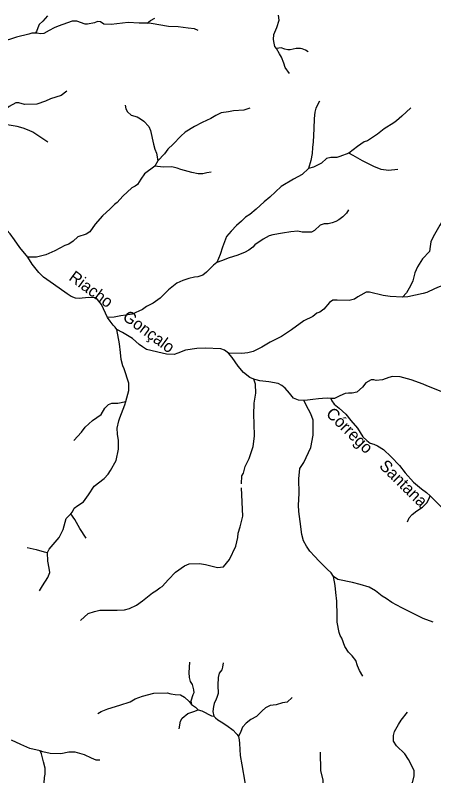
# Model space of a CAD drawing. Extents: x 717.8 to 772.7, y 8672.2 to 8728.
# Drawn here: x 756.1 to 763.19, y 8714.76 to 8727.64 of the extents above; entities that cross this region are included whole.
import ezdxf
from ezdxf.enums import TextEntityAlignment as Align

# ---------------------------------------------------------------- set-up
doc = ezdxf.new("R2010")
doc.units = 0
doc.header["$LTSCALE"] = 0.08
doc.linetypes.add('LONG_DASHED', pattern=[7.5, 6, -1.5])
doc.layers.add('61', color=7, linetype='Continuous')
doc.layers.add('9', color=7, linetype='LONG_DASHED', lineweight=25)

msp = doc.modelspace()

# ---------------------------------------------------------------- linework, layer by layer
at = {"layer": '9'}
msp.add_line((758.5196, 8725.1691), (758.4648, 8725.0777), dxfattribs=at)
for points in [[(756.6486, 8727.6249), (756.573, 8727.5356), (756.5072, 8727.4786), (756.4853, 8727.4211), (756.4612, 8727.3607), (756.4406, 8727.3316)], [(758.3358, 8727.5043), (758.3937, 8727.5448), (758.469, 8727.5876)], [(760.5259, 8727.0735), (760.4994, 8727.1071), (760.4855, 8727.166), (760.4753, 8727.2276), (760.4832, 8727.3107), (760.534, 8727.4283), (760.572, 8727.5508), (760.5609, 8727.637)], [(758.3358, 8727.5043), (758.2024, 8727.5046), (758.0148, 8727.5146), (757.7287, 8727.4781), (757.6046, 8727.4838), (757.548, 8727.5256), (757.495, 8727.5314), (757.4456, 8727.5062), (757.3301, 8727.4836), (757.2879, 8727.4846), (757.1487, 8727.5367), (757.07, 8727.5367), (756.8313, 8727.4533), (756.7625, 8727.4206), (756.678, 8727.3781), (756.5869, 8727.3274), (756.5251, 8727.3236), (756.4774, 8727.3302), (756.4406, 8727.3316)], [(759.2033, 8727.3802), (759.1405, 8727.4046), (759.0332, 8727.417), (758.8636, 8727.4417), (758.6968, 8727.4472), (758.4026, 8727.4957), (758.3358, 8727.5043)], [(756.4406, 8727.3316), (756.3851, 8727.3307), (756.3369, 8727.3185), (756.1262, 8727.2669), (755.8644, 8727.1781), (755.7217, 8727.1203), (755.5081, 8726.9775), (755.4349, 8726.8991), (755.3341, 8726.7685), (755.2591, 8726.6938), (755.139, 8726.5879), (755.0338, 8726.4895), (754.923, 8726.4081), (754.7553, 8726.2679), (754.5882, 8726.0904), (754.4922, 8726.0084), (754.3818, 8725.9344), (754.2874, 8725.8947)], [(761.0652, 8727.0151), (761.0157, 8727.0437), (760.9584, 8727.0685), (760.9313, 8727.0746), (760.8581, 8727.0723), (760.7571, 8727.0522), (760.7161, 8727.0522), (760.6658, 8727.063), (760.6076, 8727.082), (760.5259, 8727.0735)], [(760.7472, 8726.6503), (760.6744, 8726.751), (760.6528, 8726.8227), (760.6102, 8726.9245), (760.5762, 8726.981), (760.5259, 8727.0735)], [(756.9762, 8726.3485), (756.8833, 8726.2784), (756.6995, 8726.2187), (756.6152, 8726.1826), (756.4684, 8726.1324), (756.2621, 8726.1268), (756.1651, 8726.153), (756.1115, 8726.1515), (755.9995, 8726.0901), (755.8472, 8725.968), (755.7044, 8725.9013)], [(761.2537, 8726.1833), (761.1949, 8726.0606), (761.1753, 8725.9966), (761.1617, 8725.8884), (761.1573, 8725.7144), (761.1463, 8725.4937), (761.1358, 8725.394), (761.1279, 8725.2931), (761.1097, 8725.1745), (761.0668, 8725.0402)], [(757.9634, 8726.113), (757.9766, 8726.0535), (758.0068, 8726.0007), (758.0682, 8725.9469), (758.1654, 8725.9157), (758.2239, 8725.8836), (758.2833, 8725.8449), (758.3683, 8725.7514), (758.3927, 8725.6835), (758.4446, 8725.4503), (758.4673, 8725.371), (758.4937, 8725.3012), (758.5196, 8725.1691)], [(760.0753, 8726.0603), (759.9715, 8726.0308), (759.7998, 8726.0148), (759.7139, 8725.9997), (759.5889, 8725.9812), (759.4978, 8725.9402), (759.4153, 8725.8902), (759.269, 8725.8173), (759.141, 8725.7536), (758.9778, 8725.6541), (758.9058, 8725.588), (758.778, 8725.4535), (758.6897, 8725.3675), (758.6306, 8725.2916), (758.5196, 8725.1691)], [(762.8008, 8726.0673), (762.6475, 8725.9255), (762.5572, 8725.847), (762.511, 8725.815), (762.3495, 8725.7152), (762.2383, 8725.6196), (762.0697, 8725.5099), (762.0092, 8725.4924), (761.8983, 8725.4163), (761.7511, 8725.3015)], [(756.6542, 8725.4873), (756.4013, 8725.6568), (756.3419, 8725.6824), (756.2368, 8725.7241), (756.1352, 8725.7512), (756.0337, 8725.7675), (755.9011, 8725.7913), (755.766, 8725.851), (755.7044, 8725.9013)], [(761.7511, 8725.3015), (761.5977, 8725.2414), (761.5457, 8725.2269), (761.446, 8725.226), (761.371, 8725.2081), (761.2858, 8725.1297), (761.1503, 8725.0615), (761.0668, 8725.0402)], [(762.5787, 8725.0253), (762.4208, 8725.0099), (762.2958, 8725.0218), (762.1764, 8725.0749), (762.0605, 8725.1315), (761.9851, 8725.1725), (761.8253, 8725.2612), (761.7511, 8725.3015)], [(758.4648, 8725.0777), (758.2907, 8724.9489), (758.2322, 8724.8621), (758.1713, 8724.7715), (758.1351, 8724.7432), (758.0785, 8724.713), (757.9243, 8724.5702), (757.8322, 8724.4629), (757.786, 8724.4308), (757.7123, 8724.3598), (757.584, 8724.2381), (757.4585, 8724.0993), (757.3651, 8723.97), (757.3056, 8723.9312), (757.1622, 8723.8822), (757.0848, 8723.8095), (757.0131, 8723.7595), (756.9413, 8723.7369), (756.7759, 8723.6443), (756.6229, 8723.5772), (756.4627, 8723.5393), (756.3163, 8723.5385)], [(759.4222, 8724.9763), (759.3458, 8724.9678), (759.2807, 8724.9518), (759.2014, 8724.9518), (759.0929, 8724.9725), (758.9051, 8725.0254), (758.8447, 8725.0443), (758.7522, 8725.0669), (758.6069, 8725.0622), (758.4648, 8725.0777)], [(761.0668, 8725.0402), (760.9593, 8724.9385), (760.8152, 8724.8591), (760.6037, 8724.7345), (760.4143, 8724.5569), (760.3199, 8724.4756), (760.1835, 8724.3526), (760.0734, 8724.2613), (760.0018, 8724.2146), (759.9346, 8724.1482), (759.8516, 8724.0784), (759.7594, 8723.9778), (759.6776, 8723.8878), (759.6101, 8723.7062), (759.5735, 8723.5872), (759.5185, 8723.45)], [(763.5982, 8724.7803), (763.5611, 8724.6423), (763.5026, 8724.5196), (763.4686, 8724.4639), (763.4394, 8724.3752), (763.3687, 8724.2027), (763.2936, 8724.0797), (763.176, 8723.8834), (763.1407, 8723.7986), (763.129, 8723.7209), (763.1181, 8723.6332), (762.9961, 8723.5095), (762.9156, 8723.3784), (762.8687, 8723.2762), (762.836, 8723.1411), (762.7934, 8723.0515), (762.7274, 8722.9371), (762.6587, 8722.8609)], [(761.748, 8724.3382), (761.7094, 8724.2822), (761.6488, 8724.2207), (761.5845, 8724.1704), (761.5309, 8724.1421), (761.4688, 8724.1205), (761.4022, 8724.1048), (761.3353, 8724.1045), (761.2663, 8724.08), (761.1689, 8723.9898), (761.1172, 8723.9625), (760.9593, 8723.9644), (760.8888, 8723.9784), (760.7713, 8723.9671), (760.6302, 8723.9483), (760.4629, 8723.9178), (760.4044, 8723.9032), (760.2989, 8723.8467), (760.1605, 8723.7487), (760.1286, 8723.7061), (760.0604, 8723.6592), (759.9869, 8723.6166), (759.8574, 8723.5702), (759.7249, 8723.5279), (759.5939, 8723.48), (759.5185, 8723.45)], [(756.3163, 8723.5385), (756.1824, 8723.7026), (756.09, 8723.8301), (756.0192, 8723.9359), (755.9633, 8723.9978), (755.8208, 8724.0337), (755.7087, 8724.0529), (755.6195, 8724.0675)], [(757.6668, 8722.5198), (757.5669, 8722.7401), (757.4753, 8722.8486), (757.3423, 8722.8536), (757.1857, 8722.8376), (757.1249, 8722.8424), (757.0484, 8722.8726), (756.9819, 8722.9175), (756.8451, 8723.0131), (756.6931, 8723.1211), (756.5832, 8723.199), (756.5025, 8723.2789), (756.3914, 8723.4196), (756.3163, 8723.5385)], [(759.5185, 8723.45), (759.4611, 8723.4034), (759.3393, 8723.2858), (759.2771, 8723.2361), (759.1947, 8723.2054), (759.1382, 8723.2023), (759.0451, 8723.1807), (758.9394, 8723.1461), (758.8411, 8723.0997), (758.6967, 8722.9861), (758.5558, 8722.8447), (758.4407, 8722.7615), (758.328, 8722.7016), (758.2583, 8722.6537), (758.0843, 8722.5768), (757.9764, 8722.5586), (757.8925, 8722.5482), (757.7791, 8722.5251), (757.6668, 8722.5198)], [(764.1283, 8723.3948), (763.9194, 8723.3238), (763.7448, 8723.2539), (763.6375, 8723.1892), (763.538, 8723.1429), (763.5043, 8723.1083), (763.2782, 8723.0347), (763.2029, 8723.001), (763.0692, 8722.9417), (763.0088, 8722.9221), (762.7509, 8722.8653), (762.6587, 8722.8609)], [(762.6587, 8722.8609), (762.4535, 8722.8746), (762.334, 8722.8905), (762.1034, 8722.9447), (762.0472, 8722.9461), (761.9532, 8722.8968), (761.9038, 8722.8659), (761.8489, 8722.8254), (761.7555, 8722.8068), (761.5538, 8722.813), (761.479, 8722.8085), (761.4247, 8722.7714), (761.328, 8722.6581), (761.2614, 8722.6102), (761.212, 8722.5917), (761.1393, 8722.534), (760.9876, 8722.4599), (760.7822, 8722.3103), (760.6107, 8722.195), (760.4171, 8722.1002), (760.2792, 8722.013), (760.1323, 8721.9409), (760.0424, 8721.919), (759.9395, 8721.9087), (759.712, 8721.9115)], [(757.8255, 8722.3149), (757.7955, 8722.3516), (757.7619, 8722.3857), (757.7091, 8722.4534), (757.6668, 8722.5198)], [(759.712, 8721.9115), (759.6491, 8721.9648), (759.5869, 8721.9878), (759.3171, 8721.9967), (759.1778, 8721.9953), (758.9871, 8721.9671), (758.8567, 8721.9145), (758.7966, 8721.893), (758.6654, 8721.8967), (758.5925, 8721.9108), (758.3257, 8721.9782), (758.2575, 8722.0183), (758.2012, 8722.062), (758.0878, 8722.1614), (757.9208, 8722.2639), (757.8255, 8722.3149)], [(757.9743, 8721.0945), (758.0253, 8721.2793), (758.0242, 8721.4082), (757.9454, 8721.6469), (757.9252, 8721.7001), (757.8965, 8721.8088), (757.8869, 8721.926), (757.8688, 8722.0741), (757.8255, 8722.3149)], [(760.1429, 8721.4759), (760.0728, 8721.4999), (759.9688, 8721.5873), (759.8777, 8721.6932), (759.7762, 8721.8395), (759.712, 8721.9115)], [(757.2072, 8717.3871), (757.3407, 8717.5046), (757.4476, 8717.5409), (757.5382, 8717.563), (757.8268, 8717.5583), (757.953, 8717.5667), (758.0404, 8717.5874), (758.156, 8717.6448), (758.2566, 8717.7191), (758.4257, 8717.8555), (758.4859, 8717.8885), (758.5541, 8717.9384), (758.5902, 8717.9624), (758.6982, 8718.0826), (758.8183, 8718.2028), (758.9682, 8718.3107), (759.049, 8718.3465), (759.2258, 8718.3493), (759.3264, 8718.3361), (759.5258, 8718.2816), (759.6293, 8718.2929), (759.7317, 8718.4189), (759.8397, 8718.6472), (759.8699, 8718.7942), (759.8775, 8718.8675), (759.9112, 8718.9718), (759.9575, 8719.1534), (759.9321, 8719.699), (759.9425, 8719.8336), (759.9668, 8719.8796), (759.9941, 8719.9959), (760.0657, 8720.128), (760.1315, 8720.3321), (760.1522, 8720.5051), (760.1494, 8720.7222), (760.1402, 8720.8696), (760.1485, 8721.0662), (760.1785, 8721.2339), (760.171, 8721.3879), (760.1429, 8721.4759)], [(760.9875, 8721.1115), (760.8991, 8721.1201), (760.812, 8721.152), (760.7477, 8721.2384), (760.6741, 8721.3218), (760.6193, 8721.3668), (760.5573, 8721.3984), (760.3992, 8721.4285), (760.2417, 8721.4471), (760.1819, 8721.462), (760.1429, 8721.4759)], [(763.3165, 8721.2658), (763.0705, 8721.3606), (763.0118, 8721.3883), (762.807, 8721.4636), (762.684, 8721.4981), (762.6174, 8721.5145), (762.4888, 8721.5164), (762.4292, 8721.5007), (762.3188, 8721.4624), (762.2127, 8721.4518), (762.1745, 8721.4644), (762.1275, 8721.4643), (762.0377, 8721.4117), (761.985, 8721.3401), (761.8846, 8721.2522), (761.8093, 8721.234), (761.7448, 8721.237), (761.6896, 8721.2324), (761.5974, 8721.1909), (761.5089, 8721.1485), (761.4694, 8721.1454), (761.4447, 8721.1467)], [(761.4447, 8721.1467), (761.3854, 8721.1498), (761.3049, 8721.1458), (761.2378, 8721.1422), (761.139, 8721.1298), (761.0489, 8721.1189), (760.9875, 8721.1115)], [(761.4447, 8721.1467), (761.4634, 8721.1043), (761.503, 8721.0497), (761.5875, 8720.984), (761.6987, 8720.8792), (761.7858, 8720.7745), (761.895, 8720.6405), (761.9906, 8720.4968), (762.053, 8720.4318), (762.1121, 8720.3902), (762.1752, 8720.3739), (762.2376, 8720.3466), (762.337, 8720.2816), (762.4696, 8720.159), (762.6074, 8720.0101), (762.7068, 8719.8858), (762.8446, 8719.7278), (762.979, 8719.6165), (763.0656, 8719.554), (763.1251, 8719.4955)], [(757.0432, 8719.1899), (757.0759, 8719.2269), (757.1001, 8719.2873), (757.1633, 8719.3343), (757.2609, 8719.3938), (757.3436, 8719.5149), (757.4398, 8719.6593), (757.6082, 8719.7918), (757.6749, 8719.8635), (757.7163, 8719.9241), (757.8144, 8720.0936), (757.8538, 8720.2864), (757.8527, 8720.4366), (757.8325, 8720.54), (757.8283, 8720.6455), (757.8581, 8720.7648), (757.8762, 8720.817), (757.9571, 8721.0358), (757.9743, 8721.0945)], [(757.0978, 8720.4346), (757.2243, 8720.5744), (757.2894, 8720.6584), (757.413, 8720.7755), (757.5568, 8720.8766), (757.6228, 8720.9832), (757.6803, 8721.0418), (757.742, 8721.0673), (757.8421, 8721.0663), (757.9743, 8721.0945)], [(761.4898, 8718.1292), (761.4502, 8718.1952), (761.3823, 8718.2547), (761.2418, 8718.3952), (761.174, 8718.4687), (761.0929, 8718.5592), (761.0345, 8718.6431), (760.9863, 8718.7366), (760.9571, 8718.8451), (760.925, 8719.0638), (760.9052, 8719.2317), (760.9005, 8719.3401), (760.9109, 8719.5371), (760.9034, 8719.7842), (760.9204, 8719.9587), (760.992, 8720.0596), (761.1099, 8720.3169), (761.1495, 8720.5234), (761.1466, 8720.778), (761.1089, 8720.8836), (761.071, 8720.9591), (760.9875, 8721.1115)], [(762.745, 8719.0546), (762.7732, 8719.1233), (762.8213, 8719.1802), (762.9043, 8719.2426), (763.0007, 8719.3082), (763.0726, 8719.3802), (763.1067, 8719.4397), (763.1251, 8719.4955)], [(763.839, 8718.8338), (763.8154, 8718.891), (763.7298, 8719.0071), (763.6531, 8719.0739), (763.5525, 8719.1443), (763.3434, 8719.2806), (763.2997, 8719.3269), (763.1251, 8719.4955)], [(756.653, 8718.537), (756.6759, 8718.5933), (756.8456, 8718.7941), (756.9148, 8718.9283), (756.9329, 8718.9912), (756.9649, 8719.1148), (757.0432, 8719.1899)], [(757.3056, 8718.7781), (757.197, 8718.9464), (757.1111, 8719.0967), (757.0432, 8719.1899)], [(756.3037, 8718.6249), (756.46, 8718.5897), (756.5946, 8718.5481), (756.653, 8718.537)], [(756.5163, 8717.89), (756.5676, 8717.9722), (756.6552, 8718.1132), (756.6877, 8718.2), (756.6796, 8718.2714), (756.6563, 8718.3908), (756.653, 8718.537)], [(763.1811, 8717.3574), (763.0079, 8717.4207), (762.6475, 8717.6016), (762.4816, 8717.6911), (762.3829, 8717.7586), (762.3152, 8717.7985), (762.2036, 8717.8884), (762.0937, 8717.9514), (761.9439, 8717.998), (761.8132, 8718.0276), (761.5649, 8718.0797), (761.4898, 8718.1292)], [(761.9865, 8716.4452), (761.9316, 8716.5418), (761.8983, 8716.6184), (761.8679, 8716.7059), (761.8062, 8716.7896), (761.7475, 8716.8516), (761.6818, 8716.9459), (761.6303, 8717.0874), (761.6028, 8717.1305), (761.5853, 8717.1813), (761.5553, 8717.3569), (761.5528, 8717.4727), (761.5486, 8717.715), (761.5329, 8717.8616), (761.5171, 8717.9815), (761.4898, 8718.1292)], [(759.0514, 8716.6783), (759.0428, 8716.5026), (759.0498, 8716.4182), (759.0674, 8716.3532), (759.0965, 8716.3002), (759.1228, 8716.2107), (759.1261, 8716.1621), (759.1119, 8716.1246), (759.079, 8716.0208), (759.0888, 8715.9633)], [(759.6216, 8716.6701), (759.6125, 8716.5931), (759.6005, 8716.5516), (759.5548, 8716.4932), (759.5388, 8716.4207), (759.5351, 8716.2926), (759.538, 8716.1482), (759.514, 8716.0844), (759.5068, 8716.0556), (759.4741, 8715.9803), (759.4589, 8715.93), (759.4514, 8715.8469), (759.4654, 8715.7633)], [(757.5009, 8715.8111), (757.5585, 8715.8428), (757.6691, 8715.8877), (757.8755, 8715.9498), (758.0495, 8716.0091), (758.1318, 8716.0612), (758.2606, 8716.1061), (758.4523, 8716.1543), (758.6752, 8716.1629), (758.7377, 8716.1448), (758.8093, 8716.1312), (758.9034, 8716.1295), (758.9717, 8716.0875), (759.0465, 8716.0143), (759.0888, 8715.9633)], [(760.7937, 8716.0798), (760.7072, 8716.0034), (760.6289, 8715.9908), (760.5227, 8715.9557), (760.418, 8715.9461), (760.343, 8715.9096), (760.2837, 8715.8565), (760.186, 8715.7616), (760.0904, 8715.7116), (760.0116, 8715.6487), (759.9529, 8715.5787), (759.9241, 8715.5085), (759.8884, 8715.4323), (759.8819, 8715.4201)], [(758.8764, 8715.553), (758.9015, 8715.6823), (758.9314, 8715.733), (759.0273, 8715.8103), (759.1259, 8715.8432), (759.1978, 8715.8719)], [(759.0888, 8715.9633), (759.153, 8715.9175), (759.1978, 8715.8719)], [(759.1978, 8715.8719), (759.2647, 8715.8535), (759.4276, 8715.7716), (759.4654, 8715.7633)], [(759.4654, 8715.7633), (759.4928, 8715.7365), (759.5308, 8715.7038), (759.5903, 8715.6726), (759.6869, 8715.6092), (759.7927, 8715.5296), (759.8449, 8715.4717), (759.8535, 8715.4621), (759.8591, 8715.4541), (759.8819, 8715.4201)], [(762.5189, 8713.9212), (762.5321, 8714.0336), (762.5537, 8714.1416), (762.6338, 8714.2402), (762.6895, 8714.3462), (762.7262, 8714.451), (762.7469, 8714.5275), (762.8052, 8714.6021), (762.8267, 8714.6381), (762.8554, 8714.7532), (762.8554, 8714.8397), (762.8052, 8714.9479), (762.7621, 8715.0344), (762.6966, 8715.1256), (762.5584, 8715.2657), (762.5099, 8715.3411), (762.5074, 8715.4408), (762.5217, 8715.5056), (762.5894, 8715.6253), (762.6397, 8715.6972), (762.742, 8715.8361)], [(756.5244, 8715.1785), (756.3503, 8715.2195), (756.1993, 8715.2883), (756.0421, 8715.3587)], [(759.8819, 8715.4201), (759.893, 8715.3655), (759.8987, 8715.3039), (759.905, 8715.2034), (759.9117, 8715.0996), (759.938, 8714.9401), (759.99, 8714.6467), (759.9703, 8714.5208), (759.967, 8714.4305), (760.0174, 8714.2699), (760.0568, 8714.1993), (760.0794, 8714.0103), (760.1298, 8713.7807), (760.1022, 8713.6647), (760.1121, 8713.5723), (760.1309, 8713.5228), (760.1789, 8713.48), (760.2538, 8713.4108), (760.2908, 8713.4041), (760.3245, 8713.4166), (760.349, 8713.406), (760.3687, 8713.35), (760.3845, 8713.2586), (760.4042, 8713.206)], [(756.688, 8714.4531), (756.6164, 8714.5436), (756.595, 8714.6315), (756.5994, 8714.7258), (756.6082, 8714.7823), (756.6129, 8714.8878), (756.5833, 8714.9933), (756.5507, 8715.1278), (756.5244, 8715.1785)], [(757.5365, 8715.023), (757.4737, 8715.0223), (757.3971, 8715.0519), (757.2747, 8715.1127), (757.1183, 8715.1561), (757.0129, 8715.156), (756.876, 8715.1303), (756.6951, 8715.1322), (756.5711, 8715.1646), (756.5244, 8715.1785)], [(761.2653, 8715.1549), (761.2696, 8714.8484), (761.3082, 8714.6793), (761.3116, 8714.5195), (761.2902, 8714.372), (761.2808, 8714.3024), (761.255, 8714.1247), (761.2473, 8713.9607), (761.2551, 8713.795), (761.2765, 8713.6937), (761.3475, 8713.5401), (761.3653, 8713.4542), (761.3778, 8713.4159)]]:
    msp.add_lwpolyline(points, dxfattribs=at)

# ---------------------------------------------------------------- texts
at = {"layer": '61'}
for s, rotation, p in [('Riacho    Gonçalo', 323.649, (757.8523, 8722.5337)), ('Córrego    Santana', 315.551, (762.1572, 8720.0812))]:
    msp.add_text(s, height=0.2, rotation=rotation, dxfattribs=at).set_placement(p, align=Align.CENTER)

doc.saveas('drawing.dxf')
